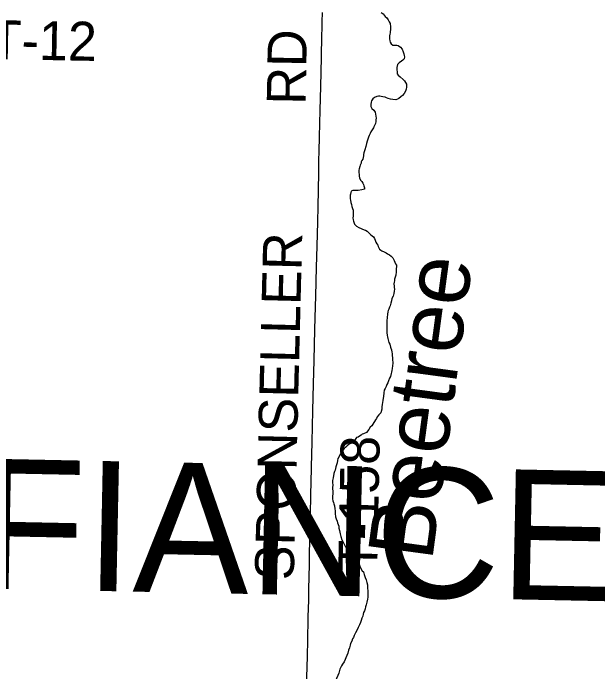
# Model space of a CAD drawing. Extents: x 2.4 to 73.1, y 4.5 to 25.6.
# Drawn here: x 34.529 to 34.9553, y 20.0736 to 20.5536 of the extents above; entities that cross this region are included whole.
import ezdxf

# ---------------------------------------------------------------- set-up
doc = ezdxf.new("R2010")
doc.units = 0
for name, color, linetype in [('GM_X_County_Text', 7, 'Continuous'), ('GM_X_Minor_River', 7, 'Continuous'), ('GM_X_Minor_River_Text', 7, 'Continuous'), ('GM_X_Township_Road', 7, 'Continuous'), ('GM_X_Township_Road_Text', 7, 'Continuous')]:
    doc.layers.add(name, color=color, linetype=linetype)

msp = doc.modelspace()

# ---------------------------------------------------------------- linework, layer by layer
at = {"layer": 'GM_X_Minor_River'}
for points in [[(34.79733, 20.55399), (34.79863, 20.55319), (34.80009, 20.55124), (34.80139, 20.55005), (34.80249, 20.54868), (34.80321, 20.54733), (34.80373, 20.54598), (34.80404, 20.5435), (34.80419, 20.54235), (34.8039, 20.53913), (34.80368, 20.53818), (34.80345, 20.53705), (34.80341, 20.53591), (34.80338, 20.53477), (34.80352, 20.53343), (34.80387, 20.53247), (34.80459, 20.53111), (34.80571, 20.53031), (34.80723, 20.53026), (34.80875, 20.53021), (34.8097, 20.52999), (34.81137, 20.5288), (34.81266, 20.52742), (34.81336, 20.5255), (34.81369, 20.52396), (34.81403, 20.52262), (34.81419, 20.52166), (34.81396, 20.52034), (34.81298, 20.51942), (34.812, 20.51869), (34.81044, 20.51741), (34.80925, 20.51612), (34.80881, 20.51404), (34.80878, 20.51309), (34.80874, 20.51195), (34.8089, 20.511), (34.80904, 20.50947), (34.80958, 20.50831), (34.81125, 20.50711), (34.81329, 20.50533), (34.8142, 20.50416), (34.81493, 20.503), (34.81565, 20.50183), (34.81578, 20.49974), (34.81554, 20.49822), (34.81511, 20.49671), (34.8141, 20.49504), (34.81291, 20.49355)], [(34.81291, 20.49355), (34.81174, 20.49264), (34.81018, 20.49136), (34.80921, 20.49082), (34.80786, 20.4903), (34.80577, 20.49056), (34.80407, 20.49099), (34.80237, 20.49143), (34.80124, 20.49185), (34.80011, 20.49226), (34.7986, 20.49269), (34.79728, 20.49293), (34.79633, 20.49296), (34.79538, 20.49299), (34.79423, 20.49284), (34.79249, 20.49213), (34.79113, 20.49104), (34.79013, 20.48974), (34.78991, 20.48861), (34.78986, 20.48709), (34.78981, 20.48557), (34.79052, 20.48402), (34.79182, 20.48284), (34.79291, 20.48147), (34.79373, 20.47707), (34.7935, 20.47593), (34.79327, 20.47461), (34.79303, 20.47309), (34.79241, 20.47178), (34.792, 20.47085), (34.79159, 20.46991), (34.79079, 20.4686), (34.78979, 20.46711), (34.78918, 20.46599), (34.78856, 20.46449), (34.78795, 20.46318), (34.78753, 20.46186), (34.7871, 20.46036), (34.78666, 20.45866), (34.78621, 20.45639), (34.78537, 20.45394), (34.78454, 20.45188), (34.78431, 20.45056), (34.78428, 20.44961), (34.78424, 20.44847), (34.78382, 20.44715), (34.78322, 20.44622), (34.78281, 20.44528), (34.78258, 20.44415), (34.78197, 20.44283), (34.78175, 20.44189), (34.78112, 20.44001), (34.78109, 20.43906), (34.78105, 20.43792), (34.78117, 20.43563), (34.78133, 20.43468), (34.78148, 20.43353), (34.78219, 20.43198), (34.78311, 20.431), (34.78383, 20.42965), (34.78437, 20.42868), (34.78472, 20.42772), (34.78506, 20.42637), (34.78522, 20.42542), (34.78311, 20.42491), (34.78062, 20.42443), (34.7789, 20.42429), (34.77757, 20.42434), (34.77662, 20.42437), (34.77546, 20.42384), (34.77505, 20.4229), (34.77482, 20.42177), (34.7746, 20.42082), (34.77456, 20.41968), (34.77471, 20.41834), (34.77487, 20.4172), (34.77519, 20.41548), (34.77553, 20.41413), (34.77586, 20.4126), (34.77639, 20.41125), (34.77692, 20.4099), (34.77689, 20.40895), (34.77682, 20.40686), (34.77678, 20.40572), (34.77674, 20.40439), (34.77689, 20.40305), (34.77705, 20.4021), (34.7774, 20.40114), (34.77793, 20.39979), (34.77941, 20.39841), (34.78109, 20.3974), (34.78484, 20.39575), (34.78578, 20.39534), (34.7871, 20.39473), (34.78858, 20.39335), (34.78986, 20.39197), (34.79172, 20.39058), (34.79245, 20.38941), (34.79298, 20.38807), (34.7935, 20.38672), (34.79423, 20.38555)], [(34.79423, 20.38555), (34.79476, 20.38439), (34.79511, 20.38343), (34.79601, 20.38169), (34.79694, 20.3809), (34.79787, 20.38029), (34.79956, 20.37967), (34.80087, 20.37886), (34.8018, 20.37826), (34.8033, 20.37745), (34.8046, 20.37646), (34.8059, 20.37527), (34.80679, 20.37334), (34.80766, 20.37084), (34.80839, 20.36987), (34.80854, 20.36872), (34.80831, 20.3674), (34.80828, 20.36625), (34.80824, 20.36511), (34.80797, 20.36265), (34.80754, 20.36114), (34.80712, 20.35983), (34.80689, 20.3585), (34.80666, 20.35756), (34.80662, 20.35623), (34.80676, 20.3547), (34.80673, 20.35356), (34.80688, 20.35241), (34.80665, 20.35109), (34.8064, 20.34939), (34.80596, 20.34731), (34.80514, 20.34562), (34.80471, 20.34393), (34.80427, 20.34223), (34.80383, 20.34034), (34.80341, 20.33921), (34.80299, 20.3379), (34.80238, 20.33677), (34.80216, 20.33583), (34.80192, 20.33413), (34.80165, 20.33185), (34.80138, 20.32939), (34.80134, 20.32806), (34.80131, 20.32692), (34.80145, 20.32558), (34.80142, 20.32444), (34.80134, 20.32197), (34.8013, 20.32083), (34.80161, 20.31873), (34.80196, 20.31777), (34.80211, 20.31643), (34.80297, 20.31355), (34.80351, 20.31239), (34.8042, 20.31027), (34.80436, 20.30932), (34.8047, 20.30816), (34.80504, 20.30663), (34.80519, 20.30549), (34.80533, 20.30377), (34.80548, 20.30262), (34.80544, 20.30148), (34.80573, 20.29862), (34.80548, 20.29654), (34.80541, 20.29463), (34.80499, 20.29313), (34.80476, 20.29199), (34.80453, 20.29086), (34.80408, 20.28878), (34.80329, 20.28767), (34.80265, 20.2856), (34.80203, 20.28409), (34.80142, 20.28297), (34.80099, 20.28147), (34.80019, 20.27997), (34.79958, 20.27885), (34.79933, 20.27696), (34.79886, 20.27431), (34.79839, 20.27147), (34.79814, 20.26958), (34.79811, 20.26863), (34.79785, 20.26654), (34.7978, 20.26502), (34.79696, 20.26239), (34.79558, 20.26091), (34.79439, 20.25943), (34.79397, 20.2583), (34.79317, 20.25719), (34.79117, 20.25402), (34.79037, 20.2529), (34.78938, 20.25179), (34.78819, 20.25012), (34.7866, 20.24808), (34.78447, 20.24701), (34.78351, 20.24685), (34.78272, 20.24593), (34.78155, 20.24521), (34.78039, 20.24467), (34.77924, 20.24433), (34.77843, 20.24284), (34.77686, 20.24118), (34.7751, 20.2399)], [(34.7751, 20.2399), (34.77394, 20.23937), (34.77257, 20.23827), (34.77159, 20.23736), (34.77042, 20.23644), (34.76924, 20.23515), (34.76822, 20.23309), (34.76703, 20.23161), (34.76641, 20.23011), (34.7658, 20.22899), (34.76556, 20.22747), (34.76513, 20.22578), (34.76471, 20.22446), (34.76428, 20.22295), (34.76404, 20.22163), (34.76363, 20.2205), (34.76321, 20.21956), (34.76279, 20.21805), (34.76231, 20.21503), (34.76186, 20.21295), (34.76182, 20.21162), (34.76194, 20.20952), (34.76189, 20.208), (34.76186, 20.20686), (34.76199, 20.20515), (34.76196, 20.20401), (34.76193, 20.20306), (34.76188, 20.20172), (34.76182, 20.19963), (34.76215, 20.1981), (34.76249, 20.19695), (34.76265, 20.19599), (34.76317, 20.19445), (34.76349, 20.19235), (34.76364, 20.19102), (34.76376, 20.18892), (34.76407, 20.18663), (34.7644, 20.18509), (34.7651, 20.18336), (34.76545, 20.1822), (34.76598, 20.18086), (34.76632, 20.1797), (34.76646, 20.17818), (34.76679, 20.17664), (34.76713, 20.1753), (34.76748, 20.17415), (34.7678, 20.17224), (34.76867, 20.16973), (34.76956, 20.16799), (34.77064, 20.16605), (34.77136, 20.1647), (34.77247, 20.16352), (34.7732, 20.16255), (34.77373, 20.16139), (34.77611, 20.15827), (34.77721, 20.15709), (34.77831, 20.15572), (34.77923, 20.15474), (34.77995, 20.15338), (34.78087, 20.15221), (34.7816, 20.15124), (34.78211, 20.14932), (34.78337, 20.14718), (34.7843, 20.14639), (34.785, 20.14447), (34.7855, 20.14236), (34.7864, 20.14061), (34.78691, 20.1387), (34.78742, 20.13697), (34.78736, 20.13507), (34.78746, 20.13202), (34.78757, 20.12973), (34.78752, 20.12802), (34.78728, 20.12651), (34.78683, 20.12424), (34.78638, 20.12235), (34.78576, 20.12085), (34.78553, 20.11953), (34.7851, 20.11802), (34.78449, 20.11671), (34.78426, 20.11558), (34.78384, 20.11426), (34.78322, 20.11276), (34.78278, 20.11106), (34.78217, 20.10956), (34.78154, 20.10787), (34.78053, 20.106), (34.77971, 20.10412), (34.77868, 20.10188), (34.77767, 20.10001), (34.77705, 20.0985), (34.77645, 20.09757), (34.77583, 20.09588), (34.77501, 20.0942), (34.77459, 20.09307), (34.77415, 20.09118), (34.77352, 20.0893), (34.77288, 20.08723), (34.77226, 20.08554), (34.77039, 20.08085), (34.7692, 20.07917)], [(34.7692, 20.07917), (34.7684, 20.07806), (34.76798, 20.07693), (34.76718, 20.07563), (34.76651, 20.0726), (34.76072, 20.05962)]]:
    msp.add_lwpolyline(points, dxfattribs=at)
at = {"layer": 'GM_X_Township_Road'}
msp.add_lwpolyline([(34.74284, 20.06576), (34.74326, 20.076), (34.74352, 20.08595), (34.74375, 20.09558), (34.74414, 20.1136), (34.74443, 20.12571), (34.74456, 20.13286), (34.7448, 20.14372), (34.74495, 20.15086), (34.74498, 20.15272), (34.745, 20.15458), (34.74505, 20.15738), (34.74514, 20.16141), (34.74527, 20.167), (34.74538, 20.17197), (34.74551, 20.17756), (34.74563, 20.18284), (34.74571, 20.18688), (34.74581, 20.19153), (34.74586, 20.19371), (34.74593, 20.19681), (34.74597, 20.1996), (34.74604, 20.20302), (34.7461, 20.20582), (34.74618, 20.20892), (34.74624, 20.21171), (34.74634, 20.21513), (34.74641, 20.21885), (34.74651, 20.22289), (34.74696, 20.24085), (34.74725, 20.25263), (34.74747, 20.26381), (34.74794, 20.28338), (34.74839, 20.30046), (34.7489, 20.32314), (34.7494, 20.3399), (34.74957, 20.34733), (34.75018, 20.36846), (34.75056, 20.38368), (34.75102, 20.40139), (34.75125, 20.41257), (34.75154, 20.42469), (34.75178, 20.43742), (34.75195, 20.44612), (34.75208, 20.45296), (34.7524, 20.46352), (34.75287, 20.48278), (34.75324, 20.50018), (34.75376, 20.5213), (34.7541, 20.53746), (34.75425, 20.54242), (34.75437, 20.54727), (34.75453, 20.55402)], dxfattribs=at)

# ---------------------------------------------------------------- texts
at = {"layer": 'GM_X_County_Text'}
msp.add_text('DEFIANCE COUNTY', height=0.094697, rotation=358.8365, dxfattribs=at).set_placement((34.3275, 20.13791))
at = {"layer": 'GM_X_Minor_River_Text'}
msp.add_text('Beetree', height=0.047375, rotation=82.3408, dxfattribs=at).set_placement((34.83436, 20.15367))
at = {"layer": 'GM_X_Township_Road_Text'}
for s, rotation, p in [('T-12', 358.9429, (34.51165, 20.52017)), ('RD', 89.0184, (34.74223, 20.48664)), ('SPONSELLER', 88.5701, (34.73347, 20.14011)), ('T-158', 88.8943, (34.79437, 20.14613))]:
    msp.add_text(s, height=0.028409, rotation=rotation, dxfattribs=at).set_placement(p)

doc.saveas('drawing.dxf')
